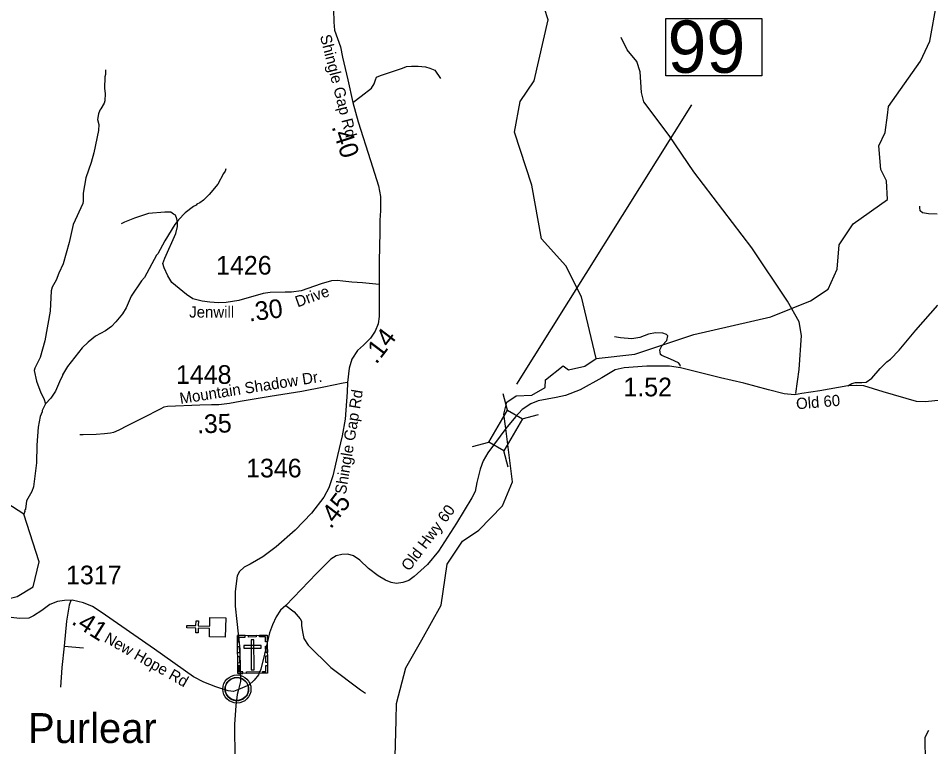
# Model space of a CAD drawing. Extents: x 1248089 to 1457196, y 820910 to 988753.
# Drawn here: x 1323531 to 1329644, y 896114 to 900993 of the extents above; entities that cross this region are included whole.
import ezdxf

# ---------------------------------------------------------------- set-up
doc = ezdxf.new("R2010")
doc.units = 0
for name, color, linetype in [('Exist Civil Demographics Community CELL', 7, 'Continuous'), ('Exist Civil Demographics Community Label', 7, 'Continuous'), ('Exist Cultural Cemetery CELL', 7, 'Continuous'), ('Exist Cultural Church CELL', 7, 'Continuous'), ('Exist Hydrographic Creek Single Shore', 7, 'Continuous'), ('Exist Hydrographic Misc Water Feature', 7, 'Continuous'), ('Exist Road Non-System Type 51', 7, 'Continuous'), ('Exist Road Secondary Structure Standard Bridge CELL', 7, 'Continuous'), ('Exist Road Secondary Structure Standard Bridge Number Label', 7, 'Continuous'), ('Exist Road Secondary Type 51 Attributed', 7, 'Continuous'), ('Exist Road Secondary Type 51 Label', 7, 'Continuous'), ('Prop GRAU CAT1 Cell', 7, 'Continuous'), ('Prop Lane Lines', 7, 'Continuous')]:
    doc.layers.add(name, color=color, linetype=linetype)

msp = doc.modelspace()

# ---------------------------------------------------------------- linework, layer by layer
at = {"layer": 'Exist Civil Demographics Community CELL'}
msp.add_lwpolyline([(1324918.1, 896513.4), (1324919.1, 896519), (1324920.9, 896525.6), (1324923.8, 896532.8), (1324926.8, 896538.5), (1324930.1, 896544.2), (1324933.8, 896549.4), (1324937.8, 896553.7), (1324942.4, 896558.3), (1324947.9, 896562.9), (1324953.4, 896566.6), (1324958.2, 896569.4), (1324963.3, 896571.9), (1324968.8, 896574.2), (1324974.4, 896576), (1324978.7, 896577.2), (1324983.6, 896577.9), (1324987.7, 896578.6), (1324994.1, 896578.9), (1324998.5, 896578.8), (1325004.2, 896578.5), (1325009.1, 896577.8), (1325014, 896576.8), (1325019, 896575.4), (1325024.1, 896573.5), (1325030.8, 896570.5), (1325037.1, 896567), (1325042.1, 896563.5), (1325047.3, 896559.5), (1325050.6, 896556.3), (1325054.7, 896552), (1325058.6, 896547.3), (1325061.7, 896542.7), (1325064.8, 896537.7), (1325067.2, 896532.5), (1325069.3, 896527.5), (1325070.8, 896522.5), (1325072.1, 896517.9), (1325073.2, 896511.8), (1325073.8, 896507.1), (1325074.1, 896501.1), (1325073.9, 896495.4), (1325073.3, 896489.7), (1325072.4, 896484.2), (1325070.8, 896478), (1325068.9, 896472.2), (1325066.6, 896467.1), (1325063.4, 896461.1), (1325060.1, 896455.8), (1325056.7, 896451.1), (1325052.5, 896446.4), (1325047.2, 896441.4), (1325042.2, 896437.3), (1325037.2, 896433.8), (1325032.8, 896431.3), (1325026, 896428.1), (1325018.9, 896425.4), (1325012.9, 896423.9), (1325006.3, 896422.6), (1325001.9, 896422.1), (1324997.4, 896421.9), (1324991.8, 896421.9), (1324987.5, 896422.3), (1324981.9, 896423), (1324976, 896424.3), (1324971.4, 896425.6), (1324966.2, 896427.5), (1324961.6, 896429.5), (1324957.7, 896431.7), (1324950.9, 896435.8), (1324945.3, 896440.1), (1324940.4, 896444.6), (1324936, 896449.4), (1324932.8, 896453.4), (1324929.8, 896457.6), (1324925.7, 896464.7), (1324924, 896468.2), (1324922.3, 896472.2), (1324919.7, 896480.4), (1324918.1, 896487.5), (1324917.5, 896492.6), (1324917.1, 896499), (1324917.1, 896503.6), (1324917.6, 896510.1)], close=True, dxfattribs=at)
for centre, radius in [((1324995.8, 896501), 94.3), ((1324995.5, 896501.3), 76.7)]:
    msp.add_circle(centre, radius, dxfattribs=at)
at = {"layer": 'Exist Cultural Cemetery CELL'}
for points in [[(1324999.8, 896859.9), (1325198.8, 896861.4), (1325200.7, 896606.8), (1325001.7, 896605.3)], [(1325000.1, 896816.6), (1325011.4, 896816.7), (1325011.2, 896848.9), (1325051.7, 896849.1), (1325051.7, 896860.3), (1324999.8, 896859.9)], [(1325073.8, 896860.4), (1325125.6, 896860.8), (1325125.7, 896849.4), (1325073.9, 896849)], [(1325199.2, 896818), (1325187.9, 896817.9), (1325187.6, 896850.1), (1325147.1, 896849.8), (1325147, 896860.9), (1325198.9, 896861.3)], [(1325000.6, 896742.4), (1325000.3, 896785.7), (1325011.7, 896785.8), (1325012, 896742.5)], [(1325041.1, 896792.1), (1325041.2, 896773.5), (1325159, 896774.3), (1325158.8, 896793)], [(1325109, 896831.4), (1325090.3, 896831.3), (1325091.8, 896628.5), (1325110.5, 896628.6)], [(1325188.4, 896744.9), (1325188, 896788.2), (1325199.4, 896788.3), (1325199.8, 896744.9)], [(1325188.8, 896678.9), (1325188.5, 896722.2), (1325199.9, 896722.3), (1325200.2, 896679)], [(1325001.1, 896675.2), (1325000.8, 896718.5), (1325012.2, 896718.6), (1325012.5, 896675.3)], [(1325034.7, 896605.6), (1325034.7, 896617), (1325012.7, 896616.9), (1325012.4, 896657.3), (1325001.2, 896657.2), (1325001.6, 896605.3)], [(1325059, 896617.2), (1325143.9, 896617.8), (1325144, 896606.4), (1325059.1, 896605.8)], [(1325167.6, 896606.5), (1325167.5, 896618), (1325189.5, 896618.2), (1325189.2, 896658.6), (1325200.4, 896658.7), (1325200.7, 896606.8)]]:
    msp.add_lwpolyline(points, close=True, dxfattribs=at)
at = {"layer": 'Exist Cultural Church CELL'}
msp.add_lwpolyline([(1324811.4, 896850.1), (1324812.9, 896907), (1324736.7, 896909.1), (1324735.9, 896877.1), (1324719.9, 896877.5), (1324720.8, 896909.5), (1324660.6, 896911.1), (1324661.1, 896927.1), (1324721.2, 896925.5), (1324722.1, 896957.5), (1324738, 896957.1), (1324737.2, 896925.1), (1324813.3, 896923), (1324815, 896980.7), (1324921.4, 896977.8), (1324917.8, 896847.2)], close=True, dxfattribs=at)
at = {"layer": 'Exist Hydrographic Creek Single Shore'}
for points in [[(1329353.3, 900345.4), (1329360.2, 900402.7), (1329575.2, 900706.9), (1329637.3, 900840.2), (1329684.2, 901098.6), (1329697.2, 901640.1), (1329735.3, 901856), (1329873.3, 902050.2), (1329900.2, 902141.5)], [(1327402.2, 898715.1), (1327304.2, 899127.4), (1327200.2, 899336.3), (1327037.2, 899516.8), (1326971.2, 899876), (1326854.2, 900229.6), (1326892.2, 900435.7), (1326987.2, 900575), (1327080.2, 900983.5), (1327057.2, 901059.4)], [(1327402.2, 898715.1), (1327661.3, 898742.7), (1328056.2, 898875.9), (1328573, 898993.8)], [(1326798, 898245.1), (1326783.8, 898341.1), (1326804.2, 898422), (1326865.5, 898465.5), (1326970.3, 898469.1), (1327060.9, 898520.7), (1327062.7, 898572.2), (1327181.7, 898666.4), (1327217.2, 898639.7), (1327327.3, 898662.9), (1327402.2, 898715.1)], [(1323204.5, 896908.5), (1323195.6, 897032.9), (1323331.5, 897072.9), (1323523.4, 897120), (1323631, 897185.6), (1323671.3, 897352.5), (1323568.8, 897671.4), (1323332, 897824.4), (1323073.3, 898048.8), (1322976.3, 898235.8)], [(1326233.7, 896830.8), (1326363.2, 897061.6), (1326403.2, 897336.6), (1326506.2, 897492.2), (1326617.3, 897565.5), (1326775.8, 897728.8), (1326841.6, 897887.9), (1326798, 898245.1)]]:
    msp.add_lwpolyline(points, dxfattribs=at)
at = {"layer": 'Exist Hydrographic Misc Water Feature'}
for points in [[(1324116.3, 900648.6), (1324115.4, 900616.6), (1324111, 900600.8), (1324108.8, 900522.9), (1324113.8, 900488.8), (1324110.5, 900440.9), (1324106, 900425), (1324084.9, 900385.7), (1324076.7, 900377.9), (1324068.1, 900354.1), (1324062.9, 900316.2), (1324070, 900282.1), (1324068.9, 900242.1), (1324036.6, 900091.1), (1324018.8, 900027.6), (1323983.9, 899924.7), (1323965, 899821.2), (1323965.5, 899769.3), (1323963.1, 899753.4), (1323899, 899611.3), (1323871.7, 899492), (1323831.6, 899349.2), (1323801.9, 899286.2), (1323784.5, 899238.7), (1323759.1, 899191.4), (1323750.5, 899167.6), (1323744.7, 899031.9), (1323709.1, 898833), (1323677.9, 898721.9), (1323642, 898650.9), (1323637.4, 898635.1), (1323653.4, 898562.6), (1323683.3, 898485.8), (1323702.2, 898447.3), (1323713, 898410.4)], [(1328573, 898993.8), (1328837.3, 899100), (1328956.3, 899179.6), (1329017.3, 899312.9), (1329030.2, 899476.9), (1329124.2, 899616.2), (1329353.3, 899779), (1329348.2, 899903.9), (1329308.3, 899980.2), (1329295.2, 900137.9), (1329339.2, 900229), (1329353.3, 900345.4)], [(1324922, 899985.5), (1324917.6, 899969.7), (1324905.1, 899954), (1324867.1, 899883.2), (1324809.1, 899812.8), (1324772.1, 899775.9), (1324747.5, 899756.7), (1324727.2, 899747.2), (1324723.1, 899741.4), (1324704.7, 899731.8), (1324649.6, 899689.5), (1324604.3, 899642.9), (1324579.4, 899611.6), (1324512.2, 899501.6), (1324465.8, 899414.9), (1324457.6, 899407.1), (1324377.3, 899257.5), (1324356.7, 899234.1), (1324287.8, 899132.2), (1324253.5, 899053.1), (1324230.4, 899013.9), (1324184.8, 898959.2), (1324156, 898930), (1324115.1, 898899.2), (1324048.1, 898863.1), (1323999, 898824.6), (1323959.9, 898785.7), (1323860.3, 898660.7), (1323826.7, 898605.6), (1323826.5, 898597.6), (1323813.8, 898574), (1323781.6, 898495), (1323750.2, 898447.9), (1323713, 898410.4)], [(1323713, 898410.4), (1323691.9, 898365.6), (1323691.7, 898357.6), (1323678.8, 898326), (1323664.8, 898254.4), (1323655.4, 898134.7), (1323654.1, 898014.8), (1323633.5, 897855.4), (1323622.7, 897823.7), (1323586.9, 897760.8), (1323579.3, 897705), (1323573.1, 897697.2), (1323574.8, 897689.2), (1323568.8, 897671.4)], [(1326061.7, 896291.8), (1326064.2, 896404.6), (1326128.2, 896642.9), (1326233.7, 896830.8)], [(1326056.3, 896048.9), (1326061.7, 896291.8)]]:
    msp.add_lwpolyline(points, dxfattribs=at)
at = {"layer": 'Exist Road Non-System Type 51'}
msp.add_line((1323839, 896787.1), (1323967.2, 896776.3), dxfattribs=at)
for points in [[(1328739.7, 898480.9), (1328761.4, 898641.9), (1328778.8, 898868.2), (1328761.4, 898959.6), (1328683.2, 899098.8), (1328444.1, 899455.6), (1328057.1, 899964.8), (1327891.9, 900208.4), (1327722.4, 900434.7), (1327705, 900495.6), (1327696.3, 900634.9), (1327674.5, 900704.5), (1327609.3, 900782.8), (1327570.2, 900865.5)], [(1325771.8, 900430), (1325829, 900472.2), (1325896.6, 900525.3), (1325915.9, 900553.1), (1325924.4, 900582.1), (1325930.4, 900599.1), (1325958.2, 900611.1), (1326104.3, 900659.5), (1326130.9, 900670.4), (1326165.9, 900672.8), (1326209.4, 900671.6), (1326258.9, 900667.9), (1326287.9, 900658.3), (1326320.5, 900645), (1326359.1, 900589.4)], [(1329686.6, 899682.1), (1329628.7, 899684.5), (1329587.6, 899689.3), (1329573.1, 899702.6), (1329569.7, 899725.1), (1329570.7, 899734.1)], [(1324507.6, 899322.9), (1324500.6, 899350.6), (1324513.9, 899387.1), (1324586.8, 899552.9), (1324596.7, 899597.7), (1324596.7, 899624.2), (1324593.4, 899649.1), (1324583.5, 899675.6), (1324571.9, 899682.2), (1324552, 899693.9), (1324512.2, 899695.5), (1324404.5, 899685.6), (1324310.1, 899654.1), (1324243.8, 899627.5), (1324220.6, 899617.6)], [(1329088, 898530.8), (1329114.7, 898547.5), (1329138.9, 898553.5), (1329182.3, 898553.5), (1329210.1, 898555.9), (1329248.8, 898583.7), (1329305.5, 898646.6), (1329350.2, 898691.3), (1329374.3, 898709.4), (1329431.1, 898771.1), (1329544.6, 898904), (1329691.6, 899072.5)], [(1327968, 898661.5), (1327963.7, 898674.6), (1327952.8, 898685.4), (1327900.6, 898709.4), (1327841.9, 898735.5), (1327833.2, 898742), (1327828.9, 898772.5), (1327841.9, 898798.6), (1327876.7, 898835.6), (1327883.2, 898866), (1327872.4, 898874.7), (1327848.4, 898883.4), (1327800.6, 898885.6), (1327752.8, 898876.9), (1327694.1, 898855.2), (1327641.9, 898846.4), (1327565.9, 898853), (1327524.6, 898859.5)], [(1323882.4, 897093.9), (1323871.6, 897063.5), (1323854.2, 896954.7), (1323839, 896787.1)], [(1325322.9, 897060.1), (1325378.5, 897018.4), (1325419.6, 896971.3), (1325429.2, 896954.4), (1325429.2, 896925.4), (1325434.1, 896883.1), (1325443.7, 896838.4), (1325472.7, 896794.8), (1325624.9, 896645), (1325824.1, 896495.1), (1325857.9, 896472.2)], [(1323839, 896787.1), (1323823.7, 896645.7), (1323815, 896513)], [(1329542.8, 895406), (1329545.5, 895441.9), (1329548.2, 895463.9), (1329553.3, 895509.6), (1329555.9, 895539.6), (1329562.9, 895581.5), (1329567.5, 895611.4), (1329574.5, 895651.3), (1329584.2, 895723.1), (1329584.4, 895735.1), (1329591.4, 895775), (1329596.2, 895810.9), (1329601.1, 895848.9), (1329604.2, 895890.8), (1329611, 895934.7), (1329612, 895972.7), (1329611, 896010.8), (1329609.7, 896048.8), (1329608.6, 896080.8), (1329607.1, 896106.9), (1329606, 896144.9), (1329606.7, 896178.9), (1329629.9, 896226.3)]]:
    msp.add_lwpolyline(points, dxfattribs=at)
at = {"layer": 'Exist Road Secondary Structure Standard Bridge CELL'}
for p, q in [((1326808.5, 898368.1), (1326779.6, 898477.6)), ((1326906.3, 898311.2), (1327015.8, 898340.1)), ((1326574, 898125.3), (1326683.4, 898154.2)), ((1326812.4, 897986.5), (1326783.5, 898095.9))]:
    msp.add_line(p, q, dxfattribs=at)
msp.add_lwpolyline([(1326683.4, 898154.2), (1326808.1, 898368.4), (1326908.1, 898310.2), (1326783.5, 898095.9)], close=True, dxfattribs=at)
at = {"layer": 'Exist Road Secondary Structure Standard Bridge Number Label'}
msp.add_line((1326871, 898543.6), (1328044.1, 900413.2), dxfattribs=at)
msp.add_lwpolyline([(1327867.9, 900990.8), (1328512.1, 900990.8), (1328512.1, 900608.5), (1327867.9, 900608.5)], close=True, dxfattribs=at)
at = {"layer": 'Exist Road Secondary Type 51 Attributed'}
for points in [[(1325689.8, 901260), (1325649.3, 901104.5), (1325643, 901051.4), (1325645.5, 900967.9), (1325650.5, 900914.4), (1325689.7, 900801.9), (1325703.6, 900732.3), (1325737.7, 900580.5), (1325771.8, 900430), (1325806.9, 900300.8), (1325890.3, 900041.5), (1325943.4, 899870.5), (1325958.6, 899799.6), (1325957.3, 899703.5), (1325953.8, 899642.1), (1325952.3, 899561.9), (1325949.7, 899364.6), (1325948.9, 899209.7)], [(1325948.9, 899209.7), (1325837.4, 899220.3), (1325765.3, 899225.4), (1325704.7, 899233), (1325668, 899236.8), (1325630.1, 899235.5), (1325559.3, 899214), (1325425.4, 899168.5), (1325360.9, 899158.4), (1325319.2, 899158.4), (1325219.4, 899155.8), (1325171.4, 899149.5), (1325009.6, 899104), (1324924.6, 899088.9), (1324871.5, 899087.6), (1324813.4, 899091.4), (1324762.9, 899099), (1324700.9, 899114.2), (1324658, 899143.3), (1324560.7, 899224.2), (1324534.1, 899267.2), (1324507.6, 899322.9)], [(1325948.9, 899209.7), (1325949, 899132), (1325949, 898995.7), (1325942.1, 898946.2), (1325922.8, 898896.6), (1325891.2, 898851.2), (1325844.5, 898804.4), (1325804.6, 898767.3), (1325766.1, 898710.8), (1325747, 898649.6), (1325735.9, 898554.7)], [(1329713.2, 898434.9), (1329608.7, 898424), (1329547.7, 898426.1), (1329325.4, 898491.6), (1329194.7, 898530.8), (1329144.6, 898533), (1329088, 898530.8), (1328901.6, 898498.2), (1328779.5, 898480.8), (1328731.6, 898472.1), (1328661.9, 898478.6), (1328557.3, 898504.8), (1328391.7, 898548.4), (1328234.9, 898585.5), (1328056.2, 898629.1), (1327966.9, 898653.1), (1327893.9, 898664), (1327741.4, 898664), (1327588.9, 898653.1), (1327530.1, 898637.8), (1327440.7, 898585.5), (1327294.8, 898504.8), (1327196.7, 898467.7), (1327133.5, 898452.5), (1327013.7, 898430.7), (1326963.6, 898411), (1326907, 898374), (1326861.2, 898323.8), (1326798, 898245.1)], [(1325735.9, 898554.7), (1325707.9, 898550.4), (1325577.8, 898523.4), (1325431.2, 898493.5), (1325218.8, 898459.1), (1325018.4, 898427.6), (1324946.6, 898412.7), (1324874.8, 898405.2), (1324825.4, 898403.7), (1324747.7, 898402.2), (1324530.8, 898393.2), (1324505.4, 898388.7), (1324481.4, 898375.2), (1324367.7, 898316.9), (1324261.6, 898264.5), (1324204.7, 898234.5), (1324168.8, 898219.5), (1324147.9, 898215.1), (1324109, 898209.1), (1324053.6, 898206.1), (1323965.4, 898203.1), (1323942.9, 898202.6)], [(1325735.9, 898554.7), (1325733.3, 898489), (1325721.4, 898307.9), (1325701.7, 898197.6), (1325668.7, 898064.1), (1325638.5, 897927.9), (1325611, 897848.1), (1325578, 897786.1), (1325496, 897678.4), (1325386, 897564.2), (1325259.4, 897454.1), (1325170.1, 897385.3), (1325084.8, 897337.1), (1325043.5, 897317.9), (1325013.3, 897289), (1324998.2, 897258.7), (1324984.5, 897155.2), (1324984.5, 897056.1), (1324995.5, 896952.9), (1325014.7, 896767.1), (1325017.5, 896622.6), (1325018.9, 896551), (1325005.9, 896497.6)], [(1326798, 898245.1), (1326677.3, 898082.2), (1326646.4, 898029), (1326624.2, 897972.4), (1326601.9, 897883.3), (1326591.6, 897823.3), (1326569.3, 897782.1), (1326467, 897611.5), (1326347, 897424.6), (1326273.3, 897335.4), (1326184.2, 897254.8), (1326148.2, 897227.4), (1326107.1, 897213.6), (1326064.3, 897208.5), (1326028.3, 897213.6), (1325990.6, 897230.8), (1325940.9, 897259.9), (1325877.5, 897308), (1325819.3, 897364.5), (1325776.4, 897392), (1325738.7, 897404), (1325697.6, 897402.3), (1325661.6, 897392), (1325623.9, 897369.7), (1325528.6, 897274.5), (1325322.9, 897060.1), (1325288.7, 897029.2), (1325257.8, 896984.6), (1325233.8, 896931.5), (1325215, 896876.6), (1325180.7, 896734.3), (1325156.7, 896633.1), (1325139.6, 896595.4), (1325112.2, 896559.4), (1325074.5, 896526.8), (1325005.9, 896497.6)], [(1325005.9, 896497.6), (1324972, 896485.3), (1324937, 896487.9), (1324854.4, 896516.5), (1324773.7, 896548), (1324705.9, 896581.5), (1324442.6, 896768.2), (1324086.4, 897014.9), (1324027.9, 897053.2), (1323968.9, 897078.8), (1323893.2, 897095.5), (1323840, 897094.5), (1323793.8, 897086.7), (1323743, 897066.3), (1323688.9, 897026.9), (1323633.8, 896990.5), (1323602.3, 896974.7), (1323542.3, 896972.7), (1323444, 896983.6), (1323400.7, 896990.5), (1323350.5, 896983.6), (1323282.6, 896950.1), (1323204.5, 896908.5)], [(1325005.9, 896497.6), (1324998.3, 896465.3), (1324988, 896390.9), (1324979.8, 896262.8), (1324981.8, 896031.3)]]:
    msp.add_lwpolyline(points, dxfattribs=at)

# ---------------------------------------------------------------- texts
at = {"layer": 'Exist Civil Demographics Community Label'}
msp.add_text('Purlear', height=200, dxfattribs=at).set_placement((1323596.5, 896139.3))
at = {"layer": 'Exist Road Secondary Structure Standard Bridge Number Label'}
msp.add_text('99', height=350, dxfattribs=at).set_placement((1327880.5, 900628.3))
at = {"layer": 'Exist Road Secondary Type 51 Label'}
for s, rotation, p in [('Shingle Gap Rd', 284.33522, (1325551.4, 900874.1)), ('Drive', 19.81581, (1325402.1, 899056.4)), ('Mountain Shadow Dr.', 8.9147, (1324618, 898409.9)), ('Shingle Gap Rd', 80.60461, (1325725.2, 897800.8)), ('Old 60', 4.79116, (1328744.7, 898373.8)), ('Old Hwy 60', 53.00651, (1326149.5, 897285.4)), ('New Hope Rd', 330.32125, (1324100.7, 896820))]:
    msp.add_text(s, height=75, rotation=rotation, dxfattribs=at).set_placement(p)
msp.add_text('Jenwill', height=75, dxfattribs=at).set_placement((1324676.3, 898988.7))
at = {"layer": 'Prop GRAU CAT1 Cell'}
for s, rotation, p in [('.40', 287.83298, (1325628.8, 900267.1)), ('.30', 7.5011, (1325078.8, 898961.6)), ('.14', 52.71105, (1325929.6, 898670.9)), ('.35', 1.73705, (1324730.2, 898212.9)), ('.45', 52.71105, (1325624.5, 897567.9)), ('.41', 327.86448, (1323881.3, 896940.5))]:
    msp.add_text(s, height=125, rotation=rotation, dxfattribs=at).set_placement(p)
msp.add_text('1.52', height=125, dxfattribs=at).set_placement((1327584.6, 898461.2))
at = {"layer": 'Prop Lane Lines'}
for s, p in [('1426', (1324856.3, 899276.6)), ('1448', (1324587.5, 898544.8)), ('1346', (1325057.3, 897918.3)), ('1317', (1323851.4, 897202.4))]:
    msp.add_text(s, height=125, dxfattribs=at).set_placement(p)

doc.saveas('drawing.dxf')
